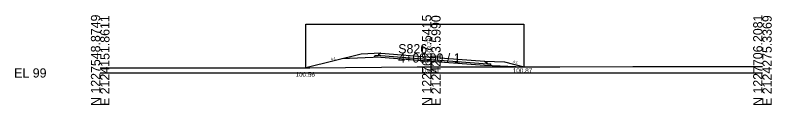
# Model space of a CAD drawing. Extents: x 2118382 to 2118616, y 1213030 to 1222057.
# Drawn here: x 2118381.9 to 2118610.4, y 1214530.1 to 1214557.3 of the extents above; entities that cross this region are included whole.
import ezdxf

# ---------------------------------------------------------------- set-up
doc = ezdxf.new("R2010")
doc.units = 0
for name, color, linetype in [('XS_CELL', 7, 'Continuous'), ('XS_M_DITCH', 7, 'Continuous'), ('XS_P_FINISHED_GRADE', 7, 'Continuous'), ('XS_P_FINISHED_GRADE_ELEV_TX', 7, 'Continuous'), ('XS_P_SUBGRADE_GRANULAR', 7, 'Continuous'), ('XS_P_SUBGRADE_PAVEMENT', 7, 'Continuous'), ('XS_P_TX_DCH', 7, 'Continuous'), ('XS_P_TX_FS_BS', 7, 'Continuous'), ('XS_X_GROUND', 7, 'Continuous'), ('XS_X_GROUND_TX', 7, 'Continuous')]:
    doc.layers.add(name, color=color, linetype=linetype)

msp = doc.modelspace()

# ---------------------------------------------------------------- linework, layer by layer
at = {"layer": 'XS_CELL'}
for p, q in [((2118507.6, 1214539.8), (2118507.6, 1214545.73)), ((2118407.6, 1214539.8), (2118507.6, 1214539.8)), ((2118507.6, 1214539.8), (2118607.6, 1214539.8))]:
    msp.add_line(p, q, dxfattribs=at)
at = {"layer": 'XS_M_DITCH'}
for p, q in [((2118469.7, 1214541.36), (2118469.7, 1214554.59)), ((2118469.7, 1214554.59), (2118535.54, 1214554.59)), ((2118535.54, 1214554.59), (2118535.54, 1214541.67))]:
    msp.add_line(p, q, dxfattribs=at)
at = {"layer": 'XS_P_FINISHED_GRADE'}
for p, q in [((2118492.37, 1214545.77), (2118486.37, 1214545.53)), ((2118492.37, 1214545.77), (2118507.6, 1214544.59)), ((2118486.37, 1214545.53), (2118469.7, 1214541.36)), ((2118507.6, 1214544.59), (2118523.69, 1214543.37)), ((2118523.69, 1214543.37), (2118529.69, 1214543.13)), ((2118529.69, 1214543.13), (2118535.54, 1214541.67))]:
    msp.add_line(p, q, dxfattribs=at)
at = {"layer": 'XS_P_SUBGRADE_GRANULAR'}
for p, q in [((2118492.37, 1214544.56), (2118480.6, 1214544.09)), ((2118491.53, 1214545.03), (2118490.53, 1214544.99)), ((2118490.53, 1214544.49), (2118490.53, 1214544.99)), ((2118492.37, 1214544.56), (2118507.6, 1214543.38)), ((2118507.6, 1214543.38), (2118523.69, 1214542.16)), ((2118523.69, 1214542.16), (2118535.46, 1214541.69)), ((2118524.56, 1214542.59), (2118525.54, 1214542.56)), ((2118525.54, 1214542.08), (2118525.54, 1214542.56))]:
    msp.add_line(p, q, dxfattribs=at)
at = {"layer": 'XS_P_SUBGRADE_PAVEMENT'}
for p, q in [((2118492.37, 1214545.77), (2118491.68, 1214545.29)), ((2118491.68, 1214545.29), (2118491.53, 1214545.03)), ((2118492.37, 1214545.06), (2118491.53, 1214545.03)), ((2118492.37, 1214545.06), (2118507.6, 1214543.88)), ((2118507.6, 1214543.88), (2118524.56, 1214542.59)), ((2118523.69, 1214543.37), (2118524.39, 1214542.88)), ((2118524.39, 1214542.88), (2118524.56, 1214542.59))]:
    msp.add_line(p, q, dxfattribs=at)
at = {"layer": 'XS_X_GROUND'}
for p, q in [((2118407.6, 1214541.3), (2118419.2, 1214541.32)), ((2118419.2, 1214541.32), (2118424.22, 1214541.3)), ((2118424.22, 1214541.3), (2118469.53, 1214541.37)), ((2118469.53, 1214541.37), (2118469.99, 1214541.36)), ((2118469.99, 1214541.36), (2118470.58, 1214541.36)), ((2118470.58, 1214541.36), (2118470.95, 1214541.37)), ((2118470.95, 1214541.37), (2118503.37, 1214541.63)), ((2118503.37, 1214541.63), (2118507.6, 1214541.63)), ((2118507.6, 1214541.63), (2118536.62, 1214541.67)), ((2118536.62, 1214541.67), (2118546.38, 1214541.64)), ((2118546.38, 1214541.64), (2118568.45, 1214541.74)), ((2118568.45, 1214541.74), (2118593.31, 1214541.75)), ((2118593.31, 1214541.75), (2118601.84, 1214541.77)), ((2118601.84, 1214541.77), (2118607.6, 1214541.78))]:
    msp.add_line(p, q, dxfattribs=at)

# ---------------------------------------------------------------- texts
at = {"layer": 'XS_CELL'}
for s, p in [('N 1227548.8749', (2118407.6, 1214529.8)), ('E 2124151.8611', (2118410.4, 1214529.8)), ('N 1227627.5415', (2118507.6, 1214529.8)), ('E 2124213.5990', (2118510.4, 1214529.8)), ('N 1227706.2081', (2118607.6, 1214529.8)), ('E 2124275.3369', (2118610.4, 1214529.8))]:
    msp.add_text(s, height=2.8, rotation=90, dxfattribs=at).set_placement(p)
for s, p in [('S826', (2118497.6, 1214545.73)), ('4+00.00 / 1', (2118497.6, 1214542.93)), ('EL 99', (2118381.6, 1214538.4))]:
    msp.add_text(s, height=2.8, dxfattribs=at).set_placement(p)
at = {"layer": 'XS_P_FINISHED_GRADE_ELEV_TX'}
msp.add_text(' 103.79', height=1.25, rotation=90, dxfattribs=at).set_placement((2118507.6, 1214544.57))
at = {"layer": 'XS_P_TX_DCH'}
for s, p in [('100.87', (2118532.18, 1214539.82)), ('100.56', (2118466.54, 1214538.64))]:
    msp.add_text(s, height=1.4, dxfattribs=at).set_placement(p)
at = {"layer": 'XS_P_TX_FS_BS'}
for rotation, p in [(14.0362, (2118477.33, 1214543.53)), (14.0362, (2118477.33, 1214543.53)), (345.9638, (2118532.14, 1214542.89))]:
    msp.add_text('4:1', height=0.8, rotation=rotation, dxfattribs=at).set_placement(p)
at = {"layer": 'XS_X_GROUND_TX'}
msp.add_text('100.83', height=1, dxfattribs=at).set_placement((2118504.95, 1214539.94))

doc.saveas('drawing.dxf')
